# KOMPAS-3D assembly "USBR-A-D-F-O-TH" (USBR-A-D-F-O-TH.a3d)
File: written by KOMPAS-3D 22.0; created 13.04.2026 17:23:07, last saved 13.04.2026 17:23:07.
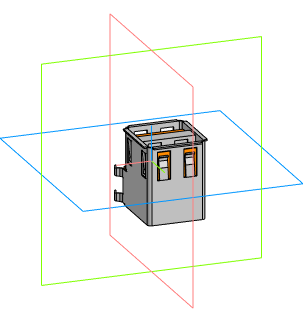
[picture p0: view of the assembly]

Document properties: Автор: Andrey; Полное имя файла: C:\Users\User1\Documents\USBR-A-D-F-O-TH.a3d

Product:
- Component [detail]: USBR-A-D-TH_p  | qty 1  | source file: USBR-A-D-TH_p.m3d
- Component [detail]: USBR-A-D-TH_b  | qty 1  | source file: USBR-A-D-TH_b.m3d
- Component [detail]: USBR-A-D-TH_s  | qty 1  | source file: USBR-A-D-TH_s.m3d
- Part/product: USBR-A-D-F-O-TH
    Комментарий: USBR-A-D-F-O-TH

Referenced files in C:\Users\User1\Documents\: USBR-A-D-TH_p.m3d, USBR-A-D-TH_b.m3d, USBR-A-D-TH_s.m3d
